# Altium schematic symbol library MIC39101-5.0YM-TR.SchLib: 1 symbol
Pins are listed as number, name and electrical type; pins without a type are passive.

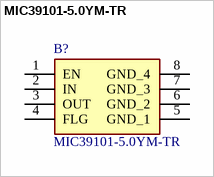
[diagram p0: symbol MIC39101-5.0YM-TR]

## MIC39101-5.0YM-TR
designator B?
LDO Voltage Regulators 1.0A 1.0% Fixed Voltage LDO; Manufacturer_Name: Microchip; Geometry.Height: 1.73mm
footprint SOIC127P599X173-8N
pins: 1 EN, 2 IN, 3 OUT, 4 FLG, 5 GND_1, 6 GND_2, 7 GND_3, 8 GND_4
